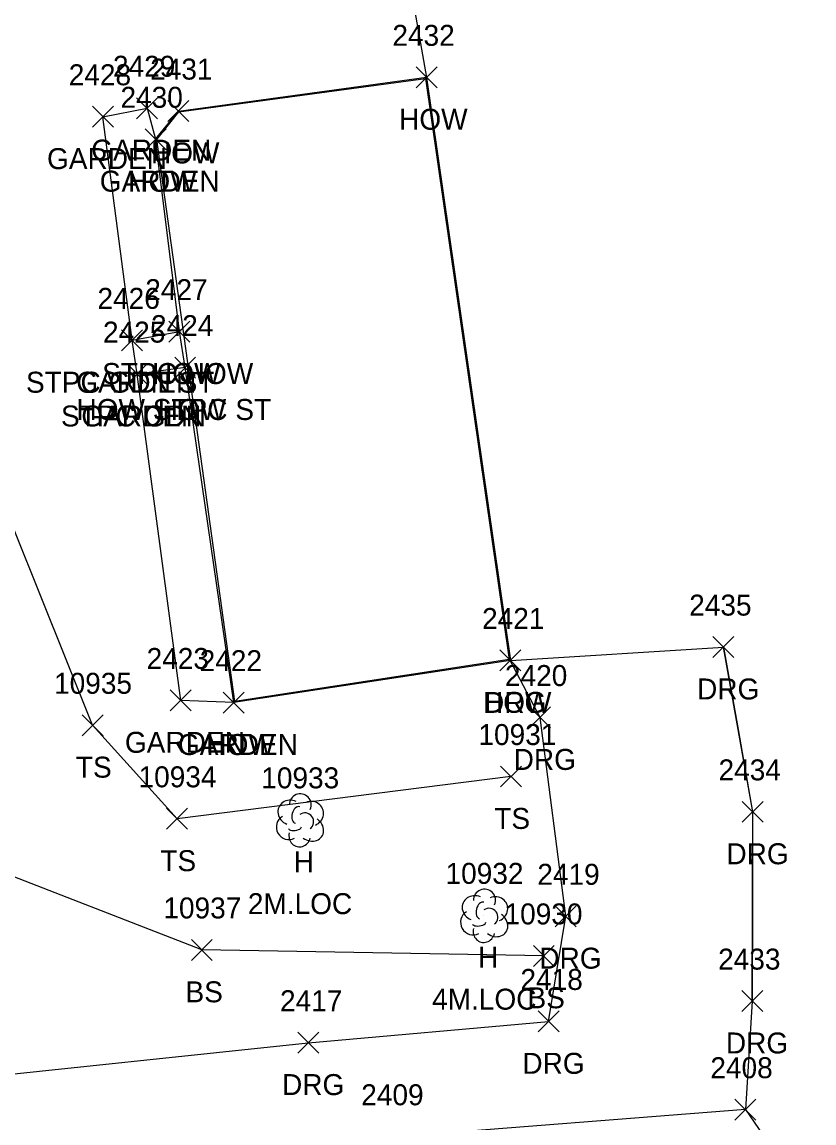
# Model space of a CAD drawing. Extents: x 1439173 to 1457902, y 641926 to 659889.
# Drawn here: x 1448092.9 to 1448168.5, y 647966.9 to 648071.9 of the extents above; entities that cross this region are included whole.
import ezdxf

# ---------------------------------------------------------------- set-up
doc = ezdxf.new("R2010")
doc.units = 0
for name, color, linetype in [('L_A', 7, 'Continuous'), ('L_C', 7, 'Continuous'), ('L_I', 7, 'Continuous'), ('L_TIC', 7, 'Continuous'), ('LAPB', 7, 'Continuous'), ('LBC', 7, 'Continuous'), ('LBF', 7, 'Continuous'), ('LELB', 7, 'Continuous'), ('Level 5', 7, 'Continuous'), ('LSOGP', 7, 'Continuous'), ('LTD', 7, 'Continuous'), ('R_A', 7, 'Continuous'), ('R_I', 7, 'Continuous'), ('R_TIC', 7, 'Continuous'), ('RDG', 7, 'Continuous')]:
    doc.layers.add(name, color=color, linetype=linetype)

msp = doc.modelspace()

# ---------------------------------------------------------------- linework, layer by layer
at = {"layer": 'L_TIC'}
for points in [[(1448130.52, 648065.64), (1448132.52, 648067.64)], [(1448132.52, 648065.64), (1448130.52, 648067.64)], [(1448130.52, 648065.64), (1448132.52, 648067.64)], [(1448132.52, 648065.64), (1448130.52, 648067.64)], [(1448103.86, 648062.69), (1448105.86, 648064.69)], [(1448105.86, 648062.69), (1448103.86, 648064.69)], [(1448099.64, 648061.88), (1448101.64, 648063.88)], [(1448101.64, 648061.88), (1448099.64, 648063.88)], [(1448106.84, 648062.42), (1448108.84, 648064.42)], [(1448108.84, 648062.42), (1448106.84, 648064.42)], [(1448104.67, 648059.73), (1448106.67, 648061.73)], [(1448106.67, 648059.73), (1448104.67, 648061.73)], [(1448104.67, 648059.73), (1448106.67, 648061.73)], [(1448106.67, 648059.73), (1448104.67, 648061.73)], [(1448102.43, 648040.55), (1448104.43, 648042.55)], [(1448104.43, 648040.55), (1448102.43, 648042.55)], [(1448102.43, 648040.55), (1448104.43, 648042.55)], [(1448104.43, 648040.55), (1448102.43, 648042.55)], [(1448106.94, 648041.38), (1448108.94, 648043.38)], [(1448108.94, 648041.38), (1448106.94, 648043.38)], [(1448106.94, 648041.38), (1448108.94, 648043.38)], [(1448108.94, 648041.38), (1448106.94, 648043.38)], [(1448102.91, 648037.33), (1448104.91, 648039.33)], [(1448104.91, 648037.33), (1448102.91, 648039.33)], [(1448102.91, 648037.33), (1448104.91, 648039.33)], [(1448104.91, 648037.33), (1448102.91, 648039.33)], [(1448107.49, 648037.95), (1448109.49, 648039.95)], [(1448109.49, 648037.95), (1448107.49, 648039.95)], [(1448107.49, 648037.95), (1448109.49, 648039.95)], [(1448109.49, 648037.95), (1448107.49, 648039.95)], [(1448138.51, 648010.01), (1448140.51, 648012.01)], [(1448140.51, 648010.01), (1448138.51, 648012.01)], [(1448138.51, 648010.01), (1448140.51, 648012.01)], [(1448140.51, 648010.01), (1448138.51, 648012.01)], [(1448107.07, 648006.2), (1448109.07, 648008.2)], [(1448109.07, 648006.2), (1448107.07, 648008.2)], [(1448112.13, 648005.99), (1448114.13, 648007.99)], [(1448114.13, 648005.99), (1448112.13, 648007.99)], [(1448112.13, 648005.99), (1448114.13, 648007.99)], [(1448114.13, 648005.99), (1448112.13, 648007.99)], [(1448098.65, 648003.83), (1448100.65, 648005.83)], [(1448100.65, 648003.83), (1448098.65, 648005.83)], [(1448138.57, 647998.94), (1448140.57, 648000.94)], [(1448140.57, 647998.94), (1448138.57, 648000.94)], [(1448106.71, 647994.91), (1448108.71, 647996.91)], [(1448108.71, 647994.91), (1448106.71, 647996.91)], [(1448109.08, 647982.4), (1448111.08, 647984.4)], [(1448111.08, 647982.4), (1448109.08, 647984.4)], [(1448141.71, 647981.83), (1448143.71, 647983.83)], [(1448143.71, 647981.83), (1448141.71, 647983.83)]]:
    msp.add_lwpolyline(points, dxfattribs=at)
at = {"layer": 'LAPB'}
for points in [[(1448103.43, 648041.55), (1448100.64, 648062.88), (1448104.86, 648063.69), (1448105.67, 648060.73)], [(1448113.13, 648006.99), (1448108.07, 648007.2), (1448103.91, 648038.33)]]:
    msp.add_lwpolyline(points, dxfattribs=at)
at = {"layer": 'LBC'}
for points in [[(1448139.51, 648011.01), (1448113.13, 648006.99), (1448108.49, 648038.95), (1448107.94, 648042.38), (1448105.67, 648060.73), (1448107.84, 648063.42), (1448131.52, 648066.64)], [(1448139.51, 648011.01), (1448131.52, 648066.64)]]:
    msp.add_lwpolyline(points, dxfattribs=at)
at = {"layer": 'LBF'}
msp.add_lwpolyline([(1448108.49, 648038.95), (1448103.91, 648038.33), (1448103.43, 648041.55), (1448107.94, 648042.38)], dxfattribs=at)
at = {"layer": 'LELB'}
for points in [[(1448142.71, 647982.83), (1448110.08, 647983.4), (1448088.77, 647991.66), (1448078.53, 648014.34), (1448071.94, 648030.86), (1448068.9, 648041.93)], [(1448139.57, 647999.94), (1448107.71, 647995.91), (1448099.65, 648004.83), (1448087.25, 648035.67)]]:
    msp.add_lwpolyline(points, dxfattribs=at)
at = {"layer": 'Level 5'}
for p, q in [((1448107.89, 648063.33), (1448131.43, 648066.52)), ((1448131.43, 648066.52), (1448139.4, 648011.1)), ((1448105.77, 648060.7), (1448107.89, 648063.33)), ((1448113.22, 648007.11), (1448105.77, 648060.7)), ((1448105.77, 648060.7), (1448105.77, 648060.7)), ((1448139.4, 648011.1), (1448113.22, 648007.11))]:
    msp.add_line(p, q, dxfattribs=at)
at = {"layer": 'LSOGP'}
msp.add_lwpolyline([(1448106.97, 648348.98), (1448089.6, 648312.64), (1448089.79, 648305.39), (1448095.09, 648287.22), (1448106.53, 648256.84), (1448108.98, 648237.24), (1448113.32, 648219.02), (1448115.51, 648199.78), (1448120.64, 648163.64), (1448121.23, 648141.68), (1448127.06, 648100.78), (1448128.34, 648084.64), (1448131.51, 648066.63), (1448139.52, 648011.01), (1448159.84, 648012.29), (1448161.24, 648004.43), (1448162.63, 647996.57), (1448162.61, 647987.54), (1448162.59, 647978.52), (1448161.94, 647968.16), (1448168.49, 647958.6)], dxfattribs=at)
at = {"layer": 'LTD'}
for p, q in [((1448119.42, 647995.81), (1448119.42, 647995.81)), ((1448119.42, 647995.81), (1448119.42, 647995.81)), ((1448137, 647986.7), (1448137, 647986.7)), ((1448137, 647986.7), (1448137, 647986.7))]:
    msp.add_line(p, q, dxfattribs=at)
for centre in [(1448119.47, 647997.24), (1448137.05, 647988.14)]:
    msp.add_arc(centre, 1.05, 335.5272, 180.9563, dxfattribs=at)
for centre, major_axis, ratio, start_param, end_param in [((1448118.63, 647996.48), (1.21, -0.51), 0.895232, 1.570796, 4.712389), ((1448120.46, 647996.39), (-1.14, -0.48), 0.949671, 1.570796, 4.712389), ((1448119.21, 647996.27), (-0.208, -0.792), 0.645439, 3.141593, 6.283185), ((1448119.92, 647995.64), (-0.5, 0.667), 0.989748, 3.141593, 6.283185), ((1448118.34, 647995.1), (0.58, -1.04), 0.959034, 3.141593, 6.283185), ((1448118.96, 647995.06), (-0.625, -0.083), 0.423636, 0, 3.141593), ((1448120.42, 647994.98), (-1.09, 0.79), 0.841452, 1.570796, 4.712389), ((1448119.42, 647994.31), (0.26, 1.06), 0.942809, 1.570796, 4.712389), ((1448136.21, 647987.37), (1.21, -0.51), 0.895232, 1.570796, 4.712389), ((1448136.79, 647987.16), (-0.208, -0.792), 0.645439, 3.141593, 6.283185), ((1448138.04, 647987.29), (-1.14, -0.48), 0.949671, 1.570796, 4.712389), ((1448135.92, 647986), (0.58, -1.04), 0.959034, 3.141593, 6.283185), ((1448137.5, 647986.54), (-0.5, 0.667), 0.989748, 3.141593, 6.283185), ((1448138, 647985.87), (-1.09, 0.79), 0.841452, 1.570796, 4.712389), ((1448136.54, 647985.95), (-0.625, -0.083), 0.423636, 0, 3.141593), ((1448137, 647985.2), (0.26, 1.06), 0.942809, 1.570796, 4.712389)]:
    msp.add_ellipse(centre, major_axis=major_axis, ratio=ratio, start_param=start_param, end_param=end_param, dxfattribs=at)
at = {"layer": 'R_TIC'}
for points in [[(1448158.84, 648011.29), (1448160.84, 648013.29)], [(1448160.84, 648011.29), (1448158.84, 648013.29)], [(1448138.51, 648010.01), (1448140.51, 648012.01)], [(1448140.51, 648010.01), (1448138.51, 648012.01)], [(1448141.35, 648004.57), (1448143.35, 648006.57)], [(1448143.35, 648004.57), (1448141.35, 648006.57)], [(1448161.64, 647995.57), (1448163.64, 647997.57)], [(1448163.64, 647995.57), (1448161.64, 647997.57)], [(1448143.8, 647985.61), (1448145.8, 647987.61)], [(1448145.8, 647985.61), (1448143.8, 647987.61)], [(1448161.6, 647977.52), (1448163.6, 647979.52)], [(1448163.6, 647977.52), (1448161.6, 647979.52)], [(1448142.17, 647975.58), (1448144.17, 647977.58)], [(1448144.17, 647975.58), (1448142.17, 647977.58)], [(1448119.24, 647973.55), (1448121.24, 647975.55)], [(1448121.24, 647973.55), (1448119.24, 647975.55)], [(1448160.94, 647967.16), (1448162.94, 647969.16)], [(1448162.94, 647967.16), (1448160.94, 647969.16)]]:
    msp.add_lwpolyline(points, dxfattribs=at)
at = {"layer": 'RDG'}
for points in [[(1448162.6, 647978.52), (1448162.64, 647996.57), (1448159.84, 648012.29)], [(1448043.29, 647976.58), (1448057.93, 647968.89), (1448085.81, 647970.9), (1448120.24, 647974.55), (1448143.17, 647976.58), (1448144.8, 647986.61), (1448142.35, 648005.57), (1448139.51, 648011.01)], [(1448161.94, 647968.16), (1448128.64, 647965.58), (1448084.79, 647959.27), (1448064.19, 647952.74), (1448054.27, 647941.14), (1448050.72, 647933.36)]]:
    msp.add_lwpolyline(points, dxfattribs=at)

# ---------------------------------------------------------------- texts
at = {"layer": 'L_A'}
for s, p in [('HOW', (1448128.9, 648061.64)), ('HOW', (1448128.9, 648061.64)), ('GARDEN', (1448099.53, 648058.69)), ('HOW', (1448105.22, 648058.42)), ('GARDEN', (1448095.31, 648057.88)), ('GARDEN', (1448100.34, 648055.73)), ('HOW', (1448103.05, 648055.73)), ('STPC HOW', (1448100.57, 648037.38)), ('HOW', (1448105.33, 648037.38)), ('STPC GDN ST', (1448093.3, 648036.55)), ('GARDEN', (1448098.1, 648036.55)), ('STPC GDN', (1448096.64, 648033.33)), ('HOW STPC ST', (1448098.12, 648033.95)), ('GARDEN', (1448098.58, 648033.33)), ('HOW', (1448105.87, 648033.95)), ('HOW', (1448136.9, 648006.01)), ('HOW', (1448136.9, 648006.01)), ('GARDEN', (1448102.74, 648002.2)), ('GARDEN', (1448107.8, 648001.99)), ('HOW', (1448110.51, 648001.99)), ('TS', (1448098.06, 647999.83)), ('TS', (1448137.98, 647994.94)), ('TS', (1448106.12, 647990.91)), ('H', (1448118.85, 647990.81)), ('H', (1448136.43, 647981.7)), ('BS', (1448108.52, 647978.4)), ('BS', (1448141.15, 647977.83))]:
    msp.add_text(s, height=2, dxfattribs=at).set_placement(p)
at = {"layer": 'L_C'}
for s, p in [('2M.LOC', (1448114.47, 647986.81)), ('4M.LOC', (1448132.05, 647977.7))]:
    msp.add_text(s, height=2, dxfattribs=at).set_placement(p)
at = {"layer": 'L_I'}
for s, p in [('2432', (1448128.26, 648069.64)), ('2432', (1448128.26, 648069.64)), ('2429', (1448101.6, 648066.69)), ('2428', (1448097.38, 648065.88)), ('2431', (1448105.15, 648066.42)), ('2430', (1448102.32, 648063.73)), ('2430', (1448102.32, 648063.73)), ('2426', (1448100.12, 648044.55)), ('2426', (1448100.12, 648044.55)), ('2427', (1448104.68, 648045.38)), ('2427', (1448104.68, 648045.38)), ('2424', (1448105.23, 648041.95)), ('2424', (1448105.23, 648041.95)), ('2425', (1448100.65, 648041.33)), ('2425', (1448100.65, 648041.33)), ('2421', (1448136.82, 648014.01)), ('2421', (1448136.82, 648014.01)), ('2423', (1448104.81, 648010.2)), ('2422', (1448109.87, 648009.99)), ('2422', (1448109.87, 648009.99)), ('10935', (1448095.98, 648007.83)), ('10931', (1448136.47, 648002.94)), ('10934', (1448104.04, 647998.91)), ('10933', (1448115.75, 647998.81)), ('10932', (1448133.33, 647989.7)), ('10937', (1448106.41, 647986.4)), ('10930', (1448138.96, 647985.83))]:
    msp.add_text(s, height=2, dxfattribs=at).set_placement(p)
at = {"layer": 'R_A'}
for p in [(1448157.33, 648007.29), (1448137, 648006.01), (1448139.83, 648000.57), (1448160.13, 647991.57), (1448142.28, 647981.61), (1448160.08, 647973.52), (1448140.66, 647971.58), (1448117.73, 647969.55)]:
    msp.add_text('DRG', height=2, dxfattribs=at).set_placement(p)
at = {"layer": 'R_I'}
for s, p in [('2435', (1448156.58, 648015.29)), ('2421', (1448136.82, 648014.01)), ('2420', (1448139, 648008.57)), ('2434', (1448159.38, 647999.57)), ('2419', (1448142.09, 647989.61)), ('2433', (1448159.34, 647981.52)), ('2418', (1448140.48, 647979.58)), ('2417', (1448117.54, 647977.55)), ('2408', (1448158.6, 647971.16)), ('2409', (1448125.29, 647968.58))]:
    msp.add_text(s, height=2, dxfattribs=at).set_placement(p)

doc.saveas('drawing.dxf')
